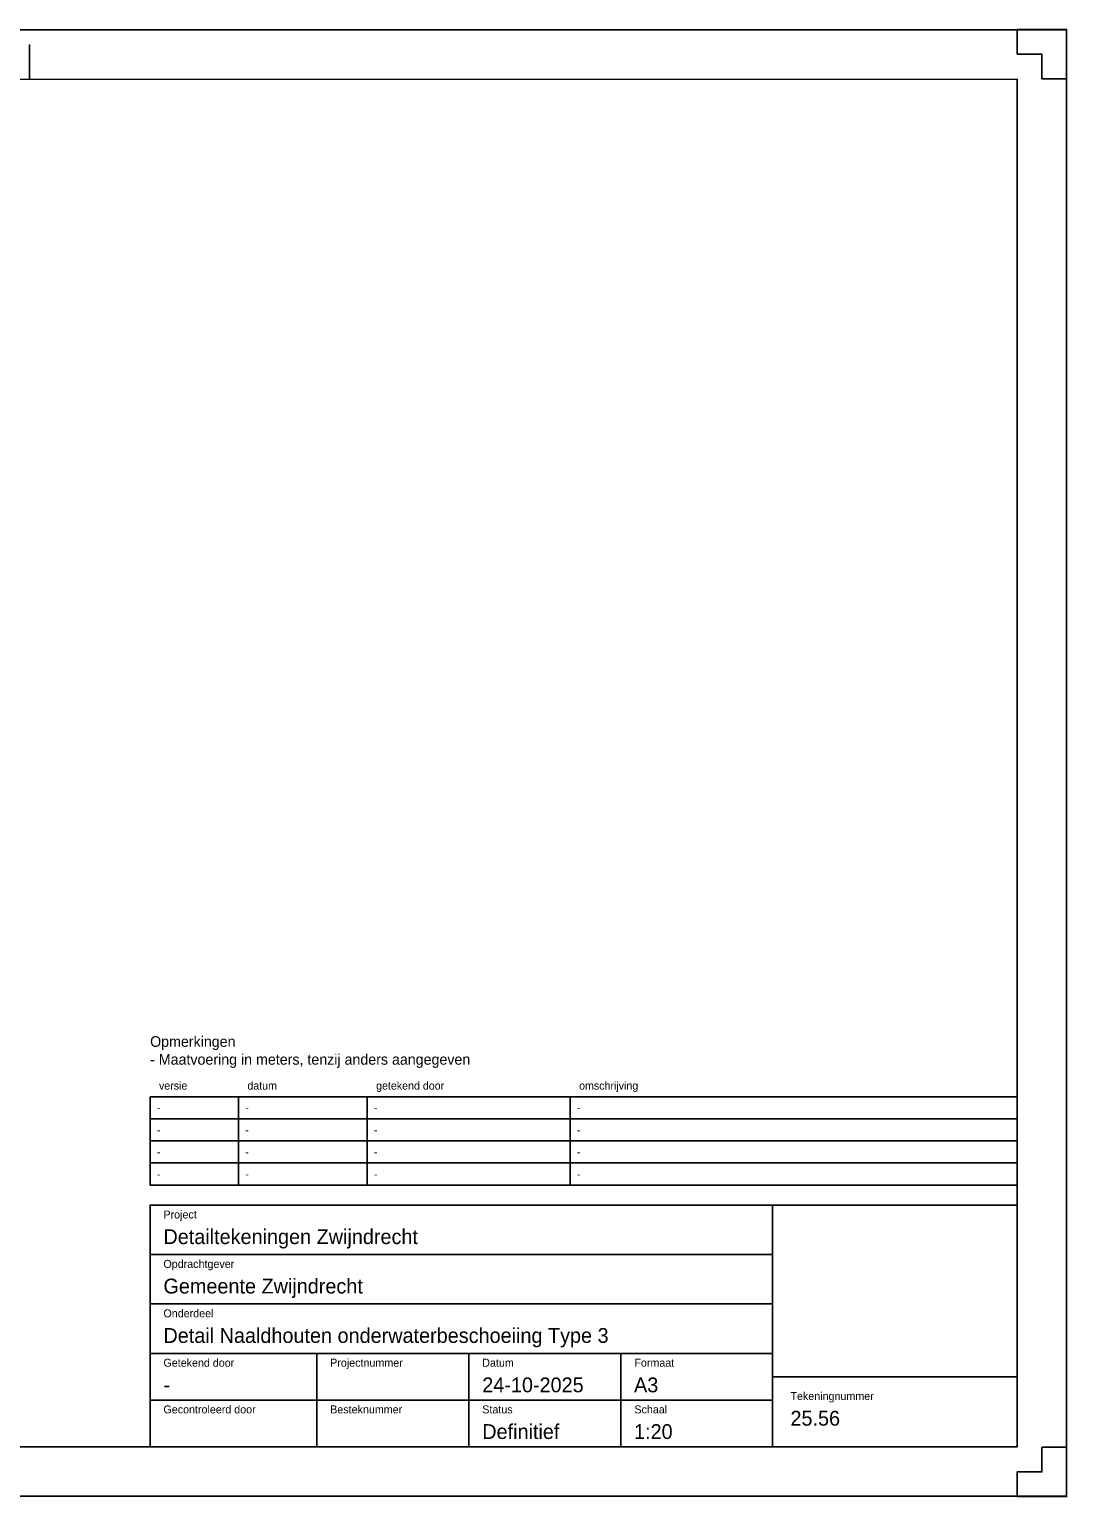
# Model space of a CAD drawing. Extents: x -1 to 419, y -1 to 296.
# Drawn here: x 209.3 to 419.2, y -0.8 to 296.2 of the extents above; entities that cross this region are included whole.
import ezdxf

# ---------------------------------------------------------------- set-up
doc = ezdxf.new("R2010")
doc.units = 0
for name, color, linetype in [('N-WE-VH-OPENVERHARDING_BETONSTRAATSTEEN-S-250', 7, 'Continuous'), ('Tekeningenhoofd', 7, 'Continuous'), ('X-XX-AL-TEKENBLAD_KADER-G', 7, 'Continuous'), ('X-XX-AL-TEKENBLAD_KADER_AFSNIJMARKERING-G', 7, 'Continuous'), ('X-XX-AL-TEKENBLAD_TITELBLOK-T', 7, 'Continuous'), ('X-XX-AL-TEKENBLAD_TITELBLOK_DIK-G', 7, 'Continuous'), ('X-XX-AL-TEKENBLAD_TITELBLOK_DUN-G', 7, 'Continuous')]:
    doc.layers.add(name, color=color, linetype=linetype)

msp = doc.modelspace()

# ---------------------------------------------------------------- linework, layer by layer
at = {"layer": 'X-XX-AL-TEKENBLAD_KADER-G'}
msp.add_line((209.26, 293.13), (209.26, 286.13), dxfattribs=at)
for points in [[(-0.7, -0.7), (419.2, -0.69), (419.21, 296.11), (-0.67, 296.1)], [(9.3, 9.3), (409.2, 9.31), (409.21, 286.11), (9.33, 286.1)]]:
    msp.add_lwpolyline(points, close=True, dxfattribs=at)
at = {"layer": 'X-XX-AL-TEKENBLAD_KADER_AFSNIJMARKERING-G'}
for points in [[(419.21, 286.22), (414.21, 286.22), (414.21, 291.22), (409.21, 291.22), (409.21, 296.22), (419.21, 296.22)], [(419.2, 9.21), (414.2, 9.21), (414.2, 4.21), (409.2, 4.21), (409.2, -0.79), (419.2, -0.79)]]:
    msp.add_lwpolyline(points, close=True, dxfattribs=at)
for points in [[(414.21, 291.22), (409.21, 291.22), (409.21, 296.22), (419.21, 296.22), (419.21, 286.22), (414.21, 286.22), (414.21, 291.22), (414.21, 291.22)], [(414.2, 4.21), (409.2, 4.21), (409.2, -0.79), (419.2, -0.79), (419.2, 9.21), (414.2, 9.21), (414.2, 4.21), (414.2, 4.21)]]:
    msp.add_lwpolyline(points, dxfattribs=at)
at = {"layer": 'X-XX-AL-TEKENBLAD_TITELBLOK_DIK-G'}
msp.add_lwpolyline([(409.2, 9.31), (233.7, 9.31), (233.7, 58.21), (409.2, 58.21)], close=True, dxfattribs=at)
at = {"layer": 'X-XX-AL-TEKENBLAD_TITELBLOK_DUN-G'}
for p, q in [((251.6, 80.17), (251.6, 75.7)), ((277.65, 80.17), (277.65, 75.7)), ((318.74, 80.17), (318.74, 75.7)), ((251.6, 75.7), (251.6, 71.22)), ((277.65, 75.7), (277.65, 71.22)), ((318.74, 75.7), (318.74, 71.22)), ((251.6, 71.22), (251.6, 66.75)), ((277.65, 71.22), (277.65, 66.75)), ((318.74, 71.22), (318.74, 66.75)), ((251.6, 66.75), (251.6, 62.27)), ((277.65, 66.75), (277.65, 62.27)), ((318.74, 66.75), (318.74, 62.27)), ((403.77, 62.27), (233.7, 62.27)), ((359.7, 9.31), (359.7, 58.21)), ((233.7, 48.21), (359.7, 48.21)), ((233.7, 38.21), (359.7, 38.21)), ((233.7, 28.21), (359.7, 28.21)), ((267.45, 9.31), (267.45, 28.21)), ((298.2, 9.31), (298.2, 28.21)), ((328.95, 9.31), (328.95, 28.21)), ((359.7, 23.49), (409.2, 23.49)), ((233.7, 18.76), (359.7, 18.76))]:
    msp.add_line(p, q, dxfattribs=at)
for points in [[(233.7, 80.17), (409.2, 80.17), (409.2, 75.7), (233.7, 75.7)], [(233.7, 75.7), (409.2, 75.7), (409.2, 71.22), (233.7, 71.22)], [(233.7, 71.22), (409.2, 71.22), (409.2, 66.75), (233.7, 66.75)], [(233.7, 66.75), (409.2, 66.75), (409.2, 62.27), (233.7, 62.27)]]:
    msp.add_lwpolyline(points, close=True, dxfattribs=at)

# ---------------------------------------------------------------- texts
at = {"layer": 'N-WE-VH-OPENVERHARDING_BETONSTRAATSTEEN-S-250'}
for s, p in [('Opmerkingen', (233.7, 90.26)), ('- Maatvoering in meters, tenzij anders aangegeven', (233.7, 86.64))]:
    msp.add_text(s, height=2.1527, dxfattribs=at).set_placement(p)
at = {"layer": 'Tekeningenhoofd'}
for s, height, p in [('versie', 1.611, (235.49, 81.6)), ('datum', 1.611, (253.39, 81.6)), ('getekend door', 1.6112, (279.44, 81.6)), ('omschrijving', 1.6112, (320.53, 81.6))]:
    msp.add_text(s, height=height, dxfattribs=at).set_placement(p)
at = {"layer": 'X-XX-AL-TEKENBLAD_TITELBLOK-T'}
for s, height, p in [('Project', 1.62, (236.4, 55.51)), ('Detailtekeningen Zwijndrecht', 3, (236.4, 50.33)), ('Opdrachtgever', 1.62, (236.4, 45.51)), ('Gemeente Zwijndrecht', 3, (236.4, 40.33)), ('Onderdeel', 1.62, (236.4, 35.51)), ('Detail Naaldhouten onderwaterbeschoeiing Type 3', 3, (236.4, 30.33)), ('Getekend door', 1.62, (236.4, 25.51)), ('Projectnummer', 1.62, (270.15, 25.51)), ('Datum', 1.62, (300.93, 25.51)), ('Formaat', 1.62, (331.72, 25.51)), ('-', 3, (236.4, 20.33)), ('24-10-2025', 3, (300.93, 20.33)), ('A3', 3, (331.65, 20.33)), ('Tekeningnummer', 1.62, (363.31, 18.76)), ('Gecontroleerd door', 1.62, (236.4, 16.06)), ('Besteknummer', 1.62, (270.15, 16.06)), ('Status', 1.62, (300.93, 16.06)), ('Schaal', 1.62, (331.72, 16.06)), ('25.56', 3, (363.31, 13.58)), ('Definitief', 3, (300.93, 10.88)), ('1:20', 3, (331.65, 10.88))]:
    msp.add_text(s, height=height, dxfattribs=at).set_placement(p)
at = {"layer": 'X-XX-AL-TEKENBLAD_TITELBLOK_DUN-G'}
for p in [(235.07, 77.13), (252.97, 77.13), (279.02, 77.13), (320.1, 77.13), (235.07, 72.65), (252.97, 72.65), (279.02, 72.65), (320.1, 72.65), (235.07, 68.18), (252.97, 68.18), (279.02, 68.18), (320.1, 68.18), (235.07, 63.7), (252.97, 63.7), (279.02, 63.7), (320.1, 63.7)]:
    msp.add_text('-', height=1.61, dxfattribs=at).set_placement(p)

doc.saveas('drawing.dxf')
